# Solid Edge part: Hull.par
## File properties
Username: m_hel
Author: m_hel
Template: Iso Metric Part.par
Last saved by: m_hel
Revision: 20
Application: Solid Edge
Accuracy: 0,990
Material: Hull
Face Style: Black (dull)
Fill Style: Normal
Virtual Style: Normal
Grouping: Uncategorized
LibraryName: Custom Materials
Coef. of Thermal Exp: 0.0
Thermal Conductivity: 0.0
Specific Heat: 0.0
Modulus of Elasticity: 0.0
Poisson's Ratio: 0.0
Yield Stress: 0.0
Ultimate Stress: 0.0
Elongation: 0.0
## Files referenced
..\Redfisher18.asm
G:\OneDriveTemp\OneDrive\Dokumendid\TLÜ tööd\3D Modelleerimine\3d modelling\veesõiduk\Deck Base.par
G:\OneDriveTemp\OneDrive\Dokumendid\TLÜ tööd\3D Modelleerimine\3d modelling\veesõiduk\Deck1.par
G:\OneDriveTemp\OneDrive\Dokumendid\TLÜ tööd\3D Modelleerimine\3d modelling\veesõiduk\Engine\Attachment.par
iduk\Deck Base.par
iduk\Deck1.par
iduk\Engine\Attachment.par
iduk\Redfisher18.asm
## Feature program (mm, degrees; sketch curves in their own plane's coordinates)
sketch for "unnamed Protrusion 1" plane through (0, 0, 0) normal (0, 0, 1) x-axis (1, 0, 0)
  line (1155, -2820) -> (-1155, -2820)
  line (-1155, -2820) -> (-1155, -36.0362)
  arc centre (2833.7179, -36.0362) radius 3988.7179 from (-1155, -36.0362) to (-221.8173, 2527.8622) cw
  line (-221.8173, 2527.8622) -> (0, 2792.2138)
  line (0, 2792.2138) -> (221.8173, 2527.8622)
  arc centre (-2833.7179, -36.0362) radius 3988.7179 from (221.8173, 2527.8622) to (1155, -36.0362) cw
  line (1155, -36.0362) -> (1155, -2820)
extrude "unnamed Protrusion 1" add finite 800 along -normal
draft "Draft_2"  Angles1 = 7 deg
sketch for "unnamed Cutout 1" plane through (0, -13.8931, -800) normal (0, 0, -1) x-axis (-1, 0, 0)
  line (0, 3287.4256) -> (0, -3532.0257)
extrude "unnamed Cutout 1" cut through along -normal
replace surface "unnamed ReplaceSurface 1"
split face "unnamed SplitFace 1"
sketch used by "ExtrudedProtrusion_3" plane through (1110.0454, -1428.0181, -366.1261) normal (0.992546, 0, -0.121869) x-axis (0, 1, 0)
extrude "ExtrudedProtrusion_3" add finite 1 along +normal
sketch for "ExtrudedProtrusion_6" #1 plane through (-1110.0454, -1428.0181, -366.1261) normal (-0.992546, 0, -0.121869) x-axis (0, -1, 0)
  line (0, 0) -> (0, 0)
  line (0, 0) -> (0, 0)
  line (0, 0) -> (0, 0)
sketch for "ExtrudedProtrusion_6" #2 plane through (-1110.0454, -1428.0181, -366.1261) normal (-0.992546, 0, -0.121869) x-axis (0, -1, 0)
sketch for "ExtrudedProtrusion_6" #3 plane through (-1110.0454, -1428.0181, -366.1261) normal (-0.992546, 0, -0.121869) x-axis (0, -1, 0)
sketch for "ExtrudedProtrusion_6" #4 plane through (-1110.0454, -1428.0181, -366.1261) normal (-0.992546, 0, -0.121869) x-axis (0, -1, 0)
sketch for "ExtrudedProtrusion_6" #5 plane through (-1110.0454, -1428.0181, -366.1261) normal (-0.992546, 0, -0.121869) x-axis (0, -1, 0)
sketch for "ExtrudedProtrusion_6" #6 plane through (-1110.0454, -1428.0181, -366.1261) normal (-0.992546, 0, -0.121869) x-axis (0, -1, 0)
sketch for "ExtrudedProtrusion_6" #7 plane through (-1110.0454, -1428.0181, -366.1261) normal (-0.992546, 0, -0.121869) x-axis (0, -1, 0)
sketch for "ExtrudedProtrusion_6" #8 plane through (-1110.0454, -1428.0181, -366.1261) normal (-0.992546, 0, -0.121869) x-axis (0, -1, 0)
sketch for "ExtrudedProtrusion_6" #9 plane through (-1110.0454, -1428.0181, -366.1261) normal (-0.992546, 0, -0.121869) x-axis (0, -1, 0)
sketch for "ExtrudedProtrusion_6" #10 plane through (-1110.0454, -1428.0181, -366.1261) normal (-0.992546, 0, -0.121869) x-axis (0, -1, 0)
sketch for "ExtrudedProtrusion_6" #11 plane through (-1110.0454, -1428.0181, -366.1261) normal (-0.992546, 0, -0.121869) x-axis (0, -1, 0)
sketch for "ExtrudedProtrusion_6" #12 plane through (-1110.0454, -1428.0181, -366.1261) normal (-0.992546, 0, -0.121869) x-axis (0, -1, 0)
sketch for "ExtrudedProtrusion_6" #13 plane through (-1110.0454, -1428.0181, -366.1261) normal (-0.992546, 0, -0.121869) x-axis (0, -1, 0)
sketch for "ExtrudedProtrusion_6" #14 plane through (-1110.0454, -1428.0181, -366.1261) normal (-0.992546, 0, -0.121869) x-axis (0, -1, 0)
sketch for "ExtrudedProtrusion_6" #15 plane through (-1110.0454, -1428.0181, -366.1261) normal (-0.992546, 0, -0.121869) x-axis (0, -1, 0)
sketch for "ExtrudedProtrusion_6" #16 plane through (-1110.0454, -1428.0181, -366.1261) normal (-0.992546, 0, -0.121869) x-axis (0, -1, 0)
sketch for "ExtrudedProtrusion_6" #17 plane through (-1110.0454, -1428.0181, -366.1261) normal (-0.992546, 0, -0.121869) x-axis (0, -1, 0)
sketch for "ExtrudedProtrusion_6" #18 plane through (-1110.0454, -1428.0181, -366.1261) normal (-0.992546, 0, -0.121869) x-axis (0, -1, 0)
sketch for "ExtrudedProtrusion_6" #19 plane through (-1110.0454, -1428.0181, -366.1261) normal (-0.992546, 0, -0.121869) x-axis (0, -1, 0)
sketch for "ExtrudedProtrusion_6" #20 plane through (-1110.0454, -1428.0181, -366.1261) normal (-0.992546, 0, -0.121869) x-axis (0, -1, 0)
sketch for "ExtrudedProtrusion_6" #21 plane through (-1110.0454, -1428.0181, -366.1261) normal (-0.992546, 0, -0.121869) x-axis (0, -1, 0)
extrude "ExtrudedProtrusion_6" add finite 1 along +normal
sketch for "unnamed Cutout 2" #1 plane through (0, -2800, -389.8553) normal (0, 1, 0) x-axis (-1, 0, 0)
sketch for "unnamed Cutout 2" #2 plane through (0, -2800, -389.8553) normal (0, 1, 0) x-axis (-1, 0, 0)
sketch for "unnamed Cutout 2" #3 plane through (0, -2800, -389.8553) normal (0, 1, 0) x-axis (-1, 0, 0)
  circle centre (-75, 324.8553) radius 10
sketch for "unnamed Cutout 2" #4 plane through (0, -2800, -389.8553) normal (0, 1, 0) x-axis (-1, 0, 0)
  circle centre (-75, 279.8553) radius 10
sketch for "unnamed Cutout 2" #5 plane through (0, -2800, -389.8553) normal (0, 1, 0) x-axis (-1, 0, 0)
  circle centre (75, 279.8553) radius 10
sketch for "unnamed Cutout 2" #6 plane through (0, -2800, -389.8553) normal (0, 1, 0) x-axis (-1, 0, 0)
  circle centre (75, 324.8553) radius 10
extrude "unnamed Cutout 2" cut through along -normal
replace surface "unnamed ReplaceSurface 2"
body pattern "unnamed BodyPattern 1"
pattern "unnamed Pattern 1"
thinwall "Thinwall_1"  Thickness = 20 mm
web network "WebNetwork_1"  Thickness = 20 mm
pattern "Pattern_1" of "WebNetwork_1" along a curve  XDirOffset = 750 mm; XDirCount = 6; XDirSpacing = 750 mm
web network "unnamed WebNetwork 1"
web network "unnamed WebNetwork 2"
web network "unnamed WebNetwork 3"
web network "unnamed WebNetwork 4"
web network "unnamed WebNetwork 5"
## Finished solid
Body 1: sheet body, 1 face, 14 edges, 14 vertices.
  Faces by surface: plane 1
  Edges by curve: line 8, circle 6
Body 2: sheet body, 1 face, 3 edges, 3 vertices.
  Faces by surface: spline 1
  Edges by curve: curve on surface 2, spline 1
Body 3: solid body, 450 faces, 1201 edges, 786 vertices.
  Faces by surface: plane 388, swept 38, offset 12, cylinder 6, cone 4, spline 2
  Edges by curve: line 1035, spline 76, intersection 70, circle 20
Bounding box of the edges (mm; curved faces can reach further): 2310.000 x 5612.214 x 953.755, from (-1155, -2820, -953.7548) to (1155, 2792.2138, 0).
Cylindrical faces by radius (mm): R10 x6
Conical faces (half-angle, radius in mm at the cone's reference point): 7 deg R3968.8669 x2, 7 deg R3988.7179 x2
Planar faces by outward normal: +y 37, +z 7, -y 38, oblique 306
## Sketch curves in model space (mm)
arc centre (0, -2820, 25351.5328) radius 25965.3068 from (0, -2820, -613.774) through (0, 2.8382, -459.8744) to (0, 2792.2138, 0)
closed spline through (-1123.1836, -2507.6663, -259.1241), (-1123.3247, -2512.3991, -257.9744), (-1123.9004, -2511.2262, -253.2863), (-1123.759, -2506.4945, -254.4373)
closed spline through (-1121.5988, -2507.6663, -272.0312), (-1121.7446, -2512.3992, -270.8435), (-1122.324, -2511.2262, -266.125), (-1122.1786, -2506.4945, -267.3089)
spline (-1122.7552, -2519.4986, -262.6131) -> (-1120.742, -2509.4452, -279.0092) -> (-1122.7552, -2499.3952, -262.6131)
spline (-1122.7552, -2499.3952, -262.6131) -> (-1124.7626, -2509.4519, -246.2641) -> (-1122.7552, -2519.4986, -262.6131)
spline (-1124.76, -2485.2424, -246.2854) -> (-1124.76, -2489.9638, -246.2854) -> (-1124.76, -2494.6852, -246.2854)
spline (-1123.8976, -2481.7042, -253.3091) -> (-1124.3288, -2483.4733, -249.7973) -> (-1124.76, -2485.2424, -246.2854)
spline (-1123.8976, -2485.2654, -253.3091) -> (-1123.8976, -2483.4848, -253.3091) -> (-1123.8976, -2481.7042, -253.3091)
spline (-1120.742, -2485.2654, -279.0092) -> (-1122.3198, -2485.2654, -266.1592) -> (-1123.8976, -2485.2654, -253.3091)
spline (-1120.742, -2494.6852, -279.0092) -> (-1120.742, -2489.9753, -279.0092) -> (-1120.742, -2485.2654, -279.0092)
spline (-1124.76, -2494.6852, -246.2854) -> (-1122.751, -2494.6852, -262.6473) -> (-1120.742, -2494.6852, -279.0092)
spline (-1119.8852, -2446.1844, -285.9873) -> (-1120.9086, -2443.2665, -277.6524) -> (-1121.932, -2440.3486, -269.3175)
spline (-1119.8852, -2455.6502, -285.9873) -> (-1119.8852, -2450.9173, -285.9873) -> (-1119.8852, -2446.1844, -285.9873)
spline (-1122.3212, -2448.6198, -266.1478) -> (-1121.1032, -2452.135, -276.0675) -> (-1119.8852, -2455.6502, -285.9873)
spline (-1124.76, -2430.8828, -246.2854) -> (-1124.6125, -2455.0376, -247.486) -> (-1122.3212, -2448.6198, -266.1478)
spline (-1123.9004, -2427.3446, -253.2863) -> (-1124.3302, -2429.1137, -249.7859) -> (-1124.76, -2430.8828, -246.2854)
spline (-1123.9004, -2430.8828, -253.2863) -> (-1123.9004, -2429.1137, -253.2863) -> (-1123.9004, -2427.3446, -253.2863)
spline (-1120.7448, -2430.8828, -278.9864) -> (-1122.3226, -2430.8828, -266.1364) -> (-1123.9004, -2430.8828, -253.2863)
spline (-1120.7448, -2440.3486, -278.9864) -> (-1120.7448, -2435.6157, -278.9864) -> (-1120.7448, -2430.8828, -278.9864)
spline (-1121.932, -2440.3486, -269.3175) -> (-1121.3384, -2440.3486, -274.152) -> (-1120.7448, -2440.3486, -278.9864)
spline (-1123.1836, -2440.3486, -259.1241) -> (-1123.2543, -2446.0817, -258.5476) -> (-1123.9004, -2445.0126, -253.2863)
spline (-1123.9004, -2440.3486, -253.2863) -> (-1123.542, -2440.3486, -256.2052) -> (-1123.1836, -2440.3486, -259.1241)
spline (-1123.9004, -2445.0126, -253.2863) -> (-1123.9004, -2442.6806, -253.2863) -> (-1123.9004, -2440.3486, -253.2863)
spline (-1124.76, -2400.1419, -246.2854) -> (-1124.76, -2412.537, -246.2854) -> (-1124.76, -2424.9322, -246.2854)
spline (-1123.9004, -2396.6037, -253.2863) -> (-1124.3302, -2398.3728, -249.7859) -> (-1124.76, -2400.1419, -246.2854)
spline (-1123.9004, -2400.1419, -253.2863) -> (-1123.9004, -2398.3728, -253.2863) -> (-1123.9004, -2396.6037, -253.2863)
spline (-1120.742, -2400.1189, -279.0092) -> (-1122.3212, -2400.1304, -266.1478) -> (-1123.9004, -2400.1419, -253.2863)
spline (-1120.742, -2421.394, -279.0092) -> (-1120.742, -2410.7565, -279.0092) -> (-1120.742, -2400.1189, -279.0092)
spline (-1121.5988, -2424.9322, -272.0312) -> (-1121.1704, -2423.1631, -275.5202) -> (-1120.742, -2421.394, -279.0092)
spline (-1121.5988, -2409.5847, -272.0312) -> (-1121.5988, -2417.2585, -272.0312) -> (-1121.5988, -2424.9322, -272.0312)
spline (-1122.324, -2409.5847, -266.125) -> (-1121.9614, -2409.5847, -269.0781) -> (-1121.5988, -2409.5847, -272.0312)
spline (-1122.324, -2417.8558, -266.125) -> (-1122.324, -2413.7203, -266.125) -> (-1122.324, -2409.5847, -266.125)
spline (-1123.1836, -2421.394, -259.1241) -> (-1122.7538, -2419.6249, -262.6245) -> (-1122.324, -2417.8558, -266.125)
spline (-1123.1836, -2409.5847, -259.1241) -> (-1123.1836, -2415.4894, -259.1241) -> (-1123.1836, -2421.394, -259.1241)
spline (-1123.9004, -2409.5847, -253.2863) -> (-1123.542, -2409.5847, -256.2052) -> (-1123.1836, -2409.5847, -259.1241)
spline (-1123.9004, -2421.394, -253.2863) -> (-1123.9004, -2415.4894, -253.2863) -> (-1123.9004, -2409.5847, -253.2863)
spline (-1124.76, -2424.9322, -246.2854) -> (-1124.3302, -2423.1631, -249.7859) -> (-1123.9004, -2421.394, -253.2863)
spline (-1123.1836, -2378.9586, -259.1241) -> (-1123.1836, -2381.888, -259.1241) -> (-1123.1836, -2384.8173, -259.1241)
spline (-1124.76, -2378.9586, -246.2854) -> (-1123.9718, -2378.9586, -252.7048) -> (-1123.1836, -2378.9586, -259.1241)
spline (-1124.76, -2369.4928, -246.2854) -> (-1124.76, -2374.2257, -246.2854) -> (-1124.76, -2378.9586, -246.2854)
spline (-1123.8976, -2365.9776, -253.3091) -> (-1124.3288, -2367.7352, -249.7973) -> (-1124.76, -2369.4928, -246.2854)
spline (-1123.8976, -2369.4928, -253.3091) -> (-1123.8976, -2367.7352, -253.3091) -> (-1123.8976, -2365.9776, -253.3091)
spline (-1120.742, -2369.4928, -279.0092) -> (-1122.3198, -2369.4928, -266.1592) -> (-1123.8976, -2369.4928, -253.3091)
spline (-1120.742, -2378.9586, -279.0092) -> (-1120.742, -2374.2257, -279.0092) -> (-1120.742, -2369.4928, -279.0092)
spline (-1122.324, -2378.9586, -266.125) -> (-1121.533, -2378.9586, -272.5671) -> (-1120.742, -2378.9586, -279.0092)
spline (-1122.324, -2384.8173, -266.125) -> (-1122.324, -2381.888, -266.125) -> (-1122.324, -2378.9586, -266.125)
spline (-1120.742, -2384.8173, -279.0092) -> (-1121.533, -2384.8173, -272.5671) -> (-1122.324, -2384.8173, -266.125)
spline (-1120.742, -2394.2372, -279.0092) -> (-1120.742, -2389.5273, -279.0092) -> (-1120.742, -2384.8173, -279.0092)
spline (-1124.76, -2394.2142, -246.2854) -> (-1122.751, -2394.2257, -262.6473) -> (-1120.742, -2394.2372, -279.0092)
spline (-1124.76, -2384.8173, -246.2854) -> (-1124.76, -2389.5158, -246.2854) -> (-1124.76, -2394.2142, -246.2854)
spline (-1123.1836, -2384.8173, -259.1241) -> (-1123.9718, -2384.8173, -252.7048) -> (-1124.76, -2384.8173, -246.2854)
spline (-1121.5988, -2338.7978, -272.0312) -> (-1121.7445, -2354.1913, -270.8442) -> (-1122.324, -2342.359, -266.125)
spline (-1120.742, -2338.7978, -279.0092) -> (-1121.1704, -2338.7978, -275.5202) -> (-1121.5988, -2338.7978, -272.0312)
spline (-1123.9004, -2360.0959, -253.2863) -> (-1122.4091, -2363.6571, -265.4318) -> (-1120.742, -2338.7978, -279.0092)
spline (-1124.76, -2363.6571, -246.2854) -> (-1124.3302, -2361.8765, -249.7859) -> (-1123.9004, -2360.0959, -253.2863)
spline (-1122.324, -2342.359, -266.125) -> (-1124.726, -2340.695, -246.5622) -> (-1124.76, -2363.6571, -246.2854)
spline (-1124.76, -2319.9351, -246.2854) -> (-1124.76, -2328.2062, -246.2854) -> (-1124.76, -2336.4773, -246.2854)
spline (-1123.9004, -2316.3969, -253.2863) -> (-1124.3302, -2318.166, -249.7859) -> (-1124.76, -2319.9351, -246.2854)
spline (-1123.9004, -2323.4963, -253.2863) -> (-1123.9004, -2319.9466, -253.2863) -> (-1123.9004, -2316.3969, -253.2863)
spline (-1121.5988, -2323.4963, -272.0312) -> (-1122.7496, -2323.4963, -262.6587) -> (-1123.9004, -2323.4963, -253.2863)
spline (-1121.5988, -2319.9581, -272.0312) -> (-1121.5988, -2321.7272, -272.0312) -> (-1121.5988, -2323.4963, -272.0312)
spline (-1120.742, -2319.9581, -279.0092) -> (-1121.1704, -2319.9581, -275.5202) -> (-1121.5988, -2319.9581, -272.0312)
spline (-1120.742, -2336.5003, -279.0092) -> (-1120.742, -2328.2292, -279.0092) -> (-1120.742, -2319.9581, -279.0092)
spline (-1121.5988, -2336.5003, -272.0312) -> (-1121.1704, -2336.5003, -275.5202) -> (-1120.742, -2336.5003, -279.0092)
spline (-1121.5988, -2332.9621, -272.0312) -> (-1121.5988, -2334.7312, -272.0312) -> (-1121.5988, -2336.5003, -272.0312)
spline (-1123.9004, -2332.9621, -253.2863) -> (-1122.7496, -2332.9621, -262.6587) -> (-1121.5988, -2332.9621, -272.0312)
spline (-1123.9004, -2336.5003, -253.2863) -> (-1123.9004, -2334.7312, -253.2863) -> (-1123.9004, -2332.9621, -253.2863)
spline (-1124.76, -2336.4773, -246.2854) -> (-1124.3302, -2336.4888, -249.7859) -> (-1123.9004, -2336.5003, -253.2863)
spline (-1124.76, -2289.2401, -246.2854) -> (-1124.76, -2301.6467, -246.2854) -> (-1124.76, -2314.0534, -246.2854)
spline (-1123.9004, -2285.7019, -253.2863) -> (-1124.3302, -2287.471, -249.7859) -> (-1124.76, -2289.2401, -246.2854)
spline (-1123.9004, -2289.2401, -253.2863) -> (-1123.9004, -2287.471, -253.2863) -> (-1123.9004, -2285.7019, -253.2863)
spline (-1120.742, -2289.2401, -279.0092) -> (-1122.3212, -2289.2401, -266.1478) -> (-1123.9004, -2289.2401, -253.2863)
spline (-1120.742, -2298.7059, -279.0092) -> (-1120.742, -2293.973, -279.0092) -> (-1120.742, -2289.2401, -279.0092)
spline (-1122.324, -2298.7059, -266.125) -> (-1121.533, -2298.7059, -272.5671) -> (-1120.742, -2298.7059, -279.0092)
spline (-1122.324, -2306.977, -266.125) -> (-1122.324, -2302.8415, -266.125) -> (-1122.324, -2298.7059, -266.125)
spline (-1123.1836, -2310.5152, -259.1241) -> (-1122.7538, -2308.7461, -262.6245) -> (-1122.324, -2306.977, -266.125)
spline (-1123.1836, -2298.7059, -259.1241) -> (-1123.1836, -2304.6106, -259.1241) -> (-1123.1836, -2310.5152, -259.1241)
spline (-1123.9004, -2298.7059, -253.2863) -> (-1123.542, -2298.7059, -256.2052) -> (-1123.1836, -2298.7059, -259.1241)
spline (-1123.9004, -2310.5152, -253.2863) -> (-1123.9004, -2304.6106, -253.2863) -> (-1123.9004, -2298.7059, -253.2863)
spline (-1124.76, -2314.0534, -246.2854) -> (-1124.3302, -2312.2843, -249.7859) -> (-1123.9004, -2310.5152, -253.2863)
spline (-1121.5988, -2268.0339, -272.0312) -> (-1122.3496, -2273.8696, -265.916) -> (-1123.7576, -2273.8696, -254.4493)
spline (-1123.9004, -2268.0339, -253.2863) -> (-1122.7496, -2268.0339, -262.6587) -> (-1121.5988, -2268.0339, -272.0312)
spline (-1123.7576, -2273.8696, -254.4493) -> (-1123.9004, -2271.3169, -253.2863) -> (-1123.9004, -2268.0339, -253.2863)
spline (-1124.76, -2258.5451, -246.2854) -> (-1124.76, -2272.0419, -246.2854) -> (-1124.3288, -2283.3354, -249.7973)
spline (-1123.9004, -2255.0069, -253.2863) -> (-1124.3302, -2256.776, -249.7859) -> (-1124.76, -2258.5451, -246.2854)
spline (-1123.9004, -2258.5451, -253.2863) -> (-1123.9004, -2256.776, -253.2863) -> (-1123.9004, -2255.0069, -253.2863)
spline (-1120.742, -2258.5451, -279.0092) -> (-1122.3212, -2258.5451, -266.1478) -> (-1123.9004, -2258.5451, -253.2863)
spline (-1124.3288, -2283.3354, -249.7973) -> (-1121.0941, -2283.3048, -276.141) -> (-1120.742, -2258.5451, -279.0092)
spline (-1124.76, -2227.8271, -246.2854) -> (-1124.76, -2240.2223, -246.2854) -> (-1124.76, -2252.6175, -246.2854)
spline (-1123.9004, -2224.2889, -253.2863) -> (-1124.3302, -2226.058, -249.7859) -> (-1124.76, -2227.8271, -246.2854)
spline (-1123.9004, -2227.8271, -253.2863) -> (-1123.9004, -2226.058, -253.2863) -> (-1123.9004, -2224.2889, -253.2863)
spline (-1120.742, -2227.8041, -279.0092) -> (-1122.3212, -2227.8156, -266.1478) -> (-1123.9004, -2227.8271, -253.2863)
spline (-1120.742, -2249.0793, -279.0092) -> (-1120.742, -2238.4417, -279.0092) -> (-1120.742, -2227.8041, -279.0092)
spline (-1121.5988, -2252.6175, -272.0312) -> (-1121.1704, -2250.8484, -275.5202) -> (-1120.742, -2249.0793, -279.0092)
spline (-1121.5988, -2237.27, -272.0312) -> (-1121.5988, -2244.9437, -272.0312) -> (-1121.5988, -2252.6175, -272.0312)
spline (-1122.324, -2237.27, -266.125) -> (-1121.9614, -2237.27, -269.0781) -> (-1121.5988, -2237.27, -272.0312)
spline (-1122.324, -2245.5411, -266.125) -> (-1122.324, -2241.4055, -266.125) -> (-1122.324, -2237.27, -266.125)
spline (-1123.1836, -2249.0793, -259.1241) -> (-1122.7538, -2247.3102, -262.6245) -> (-1122.324, -2245.5411, -266.125)
spline (-1123.1836, -2237.27, -259.1241) -> (-1123.1836, -2243.1746, -259.1241) -> (-1123.1836, -2249.0793, -259.1241)
spline (-1123.9004, -2237.27, -253.2863) -> (-1123.542, -2237.27, -256.2052) -> (-1123.1836, -2237.27, -259.1241)
spline (-1123.9004, -2249.0793, -253.2863) -> (-1123.9004, -2243.1746, -253.2863) -> (-1123.9004, -2237.27, -253.2863)
spline (-1124.76, -2252.6175, -246.2854) -> (-1124.3302, -2250.8484, -249.7859) -> (-1123.9004, -2249.0793, -253.2863)
spline (-1119.8852, -2212.4796, -285.9873) -> (-1120.9086, -2209.5617, -277.6524) -> (-1121.932, -2206.6439, -269.3175)
spline (-1119.8852, -2221.9454, -285.9873) -> (-1119.8852, -2217.2125, -285.9873) -> (-1119.8852, -2212.4796, -285.9873)
spline (-1122.3212, -2214.938, -266.1478) -> (-1121.1032, -2218.4417, -276.0675) -> (-1119.8852, -2221.9454, -285.9873)
spline (-1124.76, -2197.1781, -246.2854) -> (-1124.6135, -2221.327, -247.4778) -> (-1122.3212, -2214.938, -266.1478)
spline (-1123.9004, -2193.6399, -253.2863) -> (-1124.3302, -2195.409, -249.7859) -> (-1124.76, -2197.1781, -246.2854)
spline (-1123.9004, -2197.1781, -253.2863) -> (-1123.9004, -2195.409, -253.2863) -> (-1123.9004, -2193.6399, -253.2863)
spline (-1120.7448, -2197.1781, -278.9864) -> (-1122.3226, -2197.1781, -266.1364) -> (-1123.9004, -2197.1781, -253.2863)
spline (-1120.7448, -2206.6439, -278.9864) -> (-1120.7448, -2201.911, -278.9864) -> (-1120.7448, -2197.1781, -278.9864)
spline (-1121.932, -2206.6439, -269.3175) -> (-1121.3384, -2206.6439, -274.152) -> (-1120.7448, -2206.6439, -278.9864)
spline (-1123.1836, -2206.6439, -259.1241) -> (-1123.2543, -2212.377, -258.5476) -> (-1123.9004, -2211.3079, -253.2863)
spline (-1123.9004, -2206.6439, -253.2863) -> (-1123.542, -2206.6439, -256.2052) -> (-1123.1836, -2206.6439, -259.1241)
spline (-1123.9004, -2211.3079, -253.2863) -> (-1123.9004, -2208.9759, -253.2863) -> (-1123.9004, -2206.6439, -253.2863)
spline (-1128.2059, -2498.7845, -218.2206) -> (-1128.3454, -2540.6447, -217.0841) -> (-1129.8288, -2514.3211, -205.0028)
spline (-1125.5628, -2491.365, -239.7467) -> (-1126.8843, -2495.0748, -228.9837) -> (-1128.2059, -2498.7845, -218.2206)
spline (-1132.696, -2539.7504, -181.6513) -> (-1127.2498, -2566.1169, -226.0073) -> (-1125.5628, -2491.365, -239.7467)
spline (-1132.7115, -2539.8138, -181.5254) -> (-1132.7038, -2539.7821, -181.5884) -> (-1132.696, -2539.7504, -181.6513)
spline (-1134.1103, -2575.1357, -170.1329) -> (-1134.1103, -2553.5954, -170.1329) -> (-1132.7115, -2539.8138, -181.5254)
spline (-1136.7534, -2592.6382, -148.6068) -> (-1135.4318, -2583.887, -159.3699) -> (-1134.1103, -2575.1357, -170.1329)
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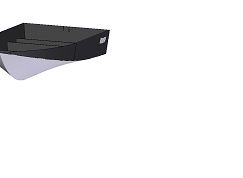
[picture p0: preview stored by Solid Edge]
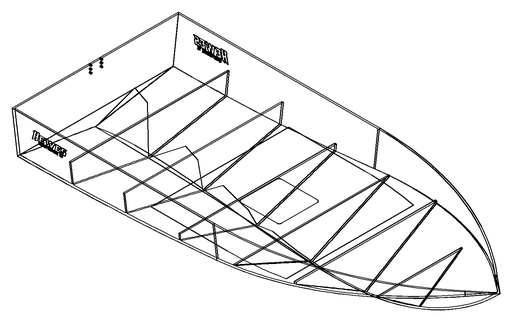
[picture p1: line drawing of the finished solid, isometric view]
